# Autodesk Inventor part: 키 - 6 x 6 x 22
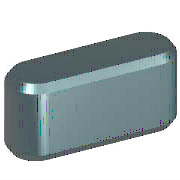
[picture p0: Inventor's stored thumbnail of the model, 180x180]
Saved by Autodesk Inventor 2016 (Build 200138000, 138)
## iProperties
IsCustomPart: 1
Created: 2012-02
Part Number: 키 - 6 x 6 x 22
Material: 강철, 연강
Description: 키 및 해당 키홈
Document SubType Name: Modeling
Standard: KS B 1311
Designer: mduedu
Standards Organization: KS
Language: ko-KR
Size Designation: 6 x 6 x 22
Categories: <MemberInstance><Categories><Category DisplayName="샤프트 부품" InternalName="7f7aeb1f-a693-4053-b835-cee3144e0d98" Mnemonic="SHFT"><Category DisplayName="키" Interna
Density: 7.86 g/cm^3
Mass: 5.79788 g
Surface Area: 5.294 cm^2
Volume: 0.737644 cm^3
Appearance: 노란색
Author: mduedu
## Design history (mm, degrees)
workplane "Work Plane1"
workplane "Work Plane2"
sketch "스케치1"
  geometry: L1 (3, 3)-(19, 3); L2 (19, -3)-(3, -3); L3 (0, 9.4)-(0, -7.4) reference; L4 (-5, 0)-(30, 0) reference; L5 (22, 0)-(22, 7); A1 r 3 centre (3, 0) between (3, 3) and (3, -3); A2 r 3 centre (19, 0) between (19, -3) and (19, 3)
  constraints: 6 end point, 5 point on circle, 4 tangent, 3 point on line, 2 centre point, 1 horizontal, 1 parallel, 1 perpendicular
  dimensions: "d0" = 3 radius of A1 (= 0.5 x PB); "d13" = 3 radius of A2 (= 0.5 x PB); "d14" = 22 distance between parallel lines of L5 L3 (= NLG)
extrude "본체1" new body sketch "스케치1" taper "d3" = 0 deg; stored distance "d4" = 10
workplane "Work Plane3"
body "Solid1"
chamfer "모따기1" distance "d8" = 0.4 (= PHH); stored, may be unused: second distance "d9" = 0.4 (= PHH), angle "d15" = 45 deg
other parameters: "d1" = -3.5 (= -PNT), "d2" = 2.5 (= PH - PNT), "NLG" = 22 [user parameter; used in 3 equation terms], "PB" = 6 [user parameter; used in 2 equation terms], "PNT" = 3.5 [user parameter; used in 2 equation terms], "PH" = 6 [user parameter; used in 1 equation term], "PHH" = 0.4 [user parameter; used in 2 equation terms], "d10" = 0, "d16" = 0, "d17" = 0, "d18" = 0, "WDMIN" = 17 [user parameter], "PLB2" = 22 (= NLG) [user parameter], "WDMAX" = 22 [user parameter], "PLB1" = 22 (= NLG) [user parameter], "RR" = 0.16 [user parameter], "PUEB" = 2.8 [user parameter]
